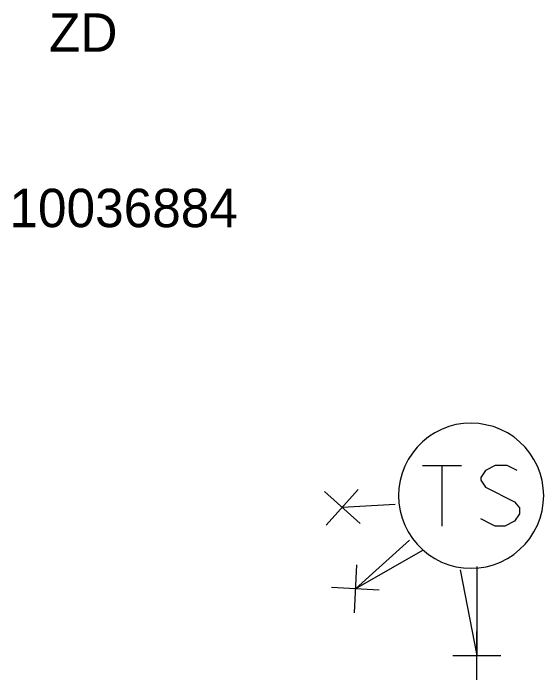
# Model space of a CAD drawing. Extents: x -737417 to -734469, y -1145580 to -1142703.
# Drawn here: x -737417.02 to -737403.21, y -1144803.12 to -1144785.77 of the extents above; entities that cross this region are included whole.
import ezdxf

# ---------------------------------------------------------------- set-up
doc = ezdxf.new("R2010")
doc.units = 0
for name, color, linetype in [('Vrstva 1', 7, 'Continuous'), ('Vrstva 25', 7, 'Continuous'), ('Vrstva 26', 7, 'Continuous'), ('Vrstva 27', 7, 'Continuous'), ('Vrstva 34', 7, 'Continuous'), ('Vrstva 59', 7, 'Continuous'), ('Vrstva 6', 7, 'Continuous')]:
    doc.layers.add(name, color=color, linetype=linetype)

# ---------------------------------------------------------------- blocks, each defined once
blk = doc.blocks.new('NN800')
at = {"layer": 'Vrstva 1'}
for points in [[(-0.442, 0.442), (0.442, -0.442)], [(-0.442, -0.442), (0.442, 0.442)]]:
    blk.add_lwpolyline(points, dxfattribs=at)
blk = doc.blocks.new('NN610')
at = {"layer": 'Vrstva 6'}
for points in [[(1.883, -0.001), (1.872, 0.196), (1.841, 0.392), (1.79, 0.583), (1.718, 0.768), (1.629, 0.943), (1.521, 1.109), (1.397, 1.263), (1.257, 1.403), (1.103, 1.527), (0.937, 1.635), (0.761, 1.725), (0.577, 1.796), (0.19, 1.878), (0.19, 1.878), (-0.007, 1.889), (-0.205, 1.878), (-0.401, 1.847), (-0.591, 1.796), (-0.777, 1.725), (-0.952, 1.635), (-1.118, 1.527), (-1.272, 1.403), (-1.412, 1.263), (-1.536, 1.109), (-1.644, 0.943), (-1.734, 0.768), (-1.805, 0.583), (-1.856, 0.392), (-1.887, 0.196), (-1.898, -0.001), (-1.887, -0.199), (-1.856, -0.395), (-1.805, -0.585), (-1.734, -0.77), (-1.644, -0.946), (-1.536, -1.112), (-1.411, -1.266), (-1.272, -1.405), (-1.118, -1.53), (-0.952, -1.638), (-0.776, -1.728), (-0.591, -1.799), (-0.401, -1.85), (-0.205, -1.881), (-0.007, -1.892), (0.19, -1.881), (0.385, -1.85), (0.577, -1.799), (0.761, -1.728), (0.937, -1.638), (1.103, -1.53), (1.257, -1.405), (1.397, -1.266), (1.521, -1.112), (1.629, -0.946), (1.718, -0.77), (1.79, -0.585), (1.841, -0.395), (1.872, -0.199), (1.883, -0.001)], [(-1.269, 0.782), (-0.261, 0.782)], [(-0.765, 0.782), (-0.765, -0.792)], [(1.188, 0.656), (0.936, 0.782), (0.621, 0.782), (0.369, 0.656), (0.243, 0.468), (0.243, 0.404), (0.369, 0.216), (1.125, -0.162), (1.251, -0.32), (1.251, -0.478), (1.125, -0.666), (0.873, -0.792), (0.621, -0.792), (0.495, -0.73), (0.243, -0.604)]]:
    blk.add_lwpolyline(points, dxfattribs=at)

msp = doc.modelspace()

# ---------------------------------------------------------------- linework, layer by layer
at = {"layer": 'Vrstva 59'}
for points in [[(-737407.071, -1144798.554), (-737408.45, -1144798.631)], [(-737406.702, -1144799.486), (-737408.11, -1144800.749)], [(-737406.362, -1144799.758), (-737408.11, -1144800.749)], [(-737404.943, -1144800.173), (-737404.943, -1144802.491)], [(-737405.38, -1144800.254), (-737404.943, -1144802.491)]]:
    msp.add_lwpolyline(points, dxfattribs=at)

# ---------------------------------------------------------------- block references
at = {"layer": 'Vrstva 25'}
msp.add_blockref('NN610', (-737405.089, -1144798.326), dxfattribs=at)
at = {"layer": 'Vrstva 34'}
for p, rotation in [((-737408.45, -1144798.631), -176.77547717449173), ((-737408.11, -1144800.749), -138.12213028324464), ((-737404.943, -1144802.491), 45)]:
    msp.add_blockref('NN800', p, dxfattribs=dict(at, rotation=rotation))

# ---------------------------------------------------------------- texts
at = {"layer": 'Vrstva 26'}
msp.add_text('10036884', height=1, dxfattribs=at).set_placement((-737417.117, -1144791.34))
at = {"layer": 'Vrstva 27'}
msp.add_text('ZD', height=1, dxfattribs=at).set_placement((-737416.086, -1144786.774))

doc.saveas('drawing.dxf')
